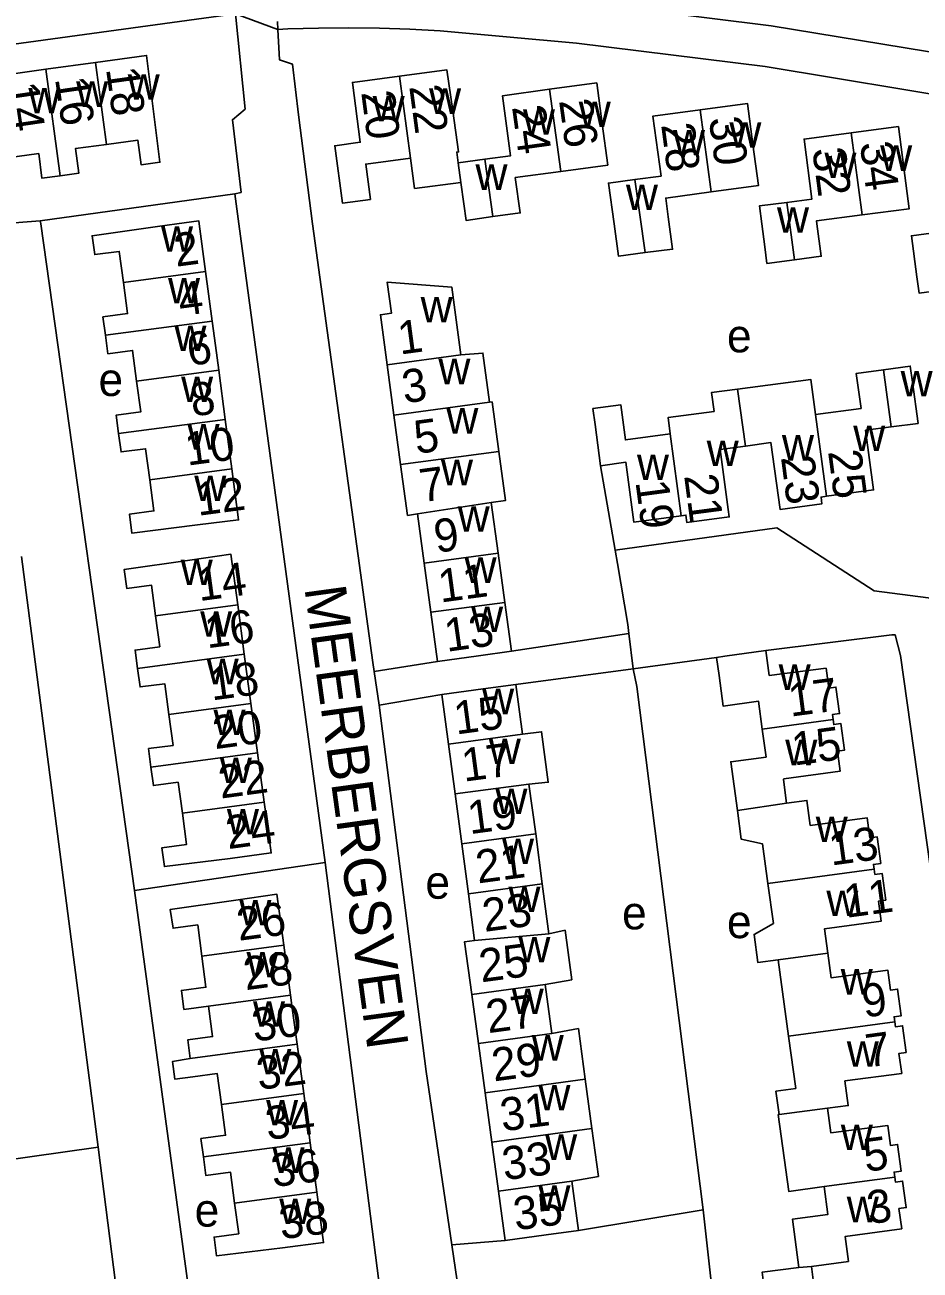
# Model space of a CAD drawing. Extents: x 162667 to 164645, y 379003 to 382150.
# Drawn here: x 163512.2 to 163620.3, y 381373.6 to 381524 of the extents above; entities that cross this region are included whole.
import ezdxf

# ---------------------------------------------------------------- set-up
doc = ezdxf.new("R2010")
doc.units = 0
for name, color, linetype in [('BLT_Basislijn', 7, 'Continuous'), ('BLT_Bebouwing', 7, 'Continuous'), ('BLT_Centroide', 7, 'Continuous'), ('BLT_Huisnummer', 7, 'Continuous'), ('BLT_Huisnummer_ tussenligend', 7, 'Continuous'), ('BLT_Onderverdeling_panden', 7, 'Continuous'), ('BLT_Straatnaam', 7, 'Continuous'), ('BLT_Vlakafsluiter', 7, 'Continuous')]:
    doc.layers.add(name, color=color, linetype=linetype)

msp = doc.modelspace()

# ---------------------------------------------------------------- linework, layer by layer
at = {"layer": 'BLT_Basislijn'}
for p, q in [((163463.77, 381515.19), (163537.61, 381525.38)), ((163542.68, 381524.44), (163542.74, 381523.47)), ((163514.05, 381500.36), (163537.54, 381503.62)), ((163583.46, 381460.55), (163581.71, 381470.77)), ((163511.79, 381459.82), (163521.06, 381388.45)), ((163583.74, 381458.96), (163583.46, 381460.55)), ((163585.13, 381450.52), (163570.94, 381448.36)), ((163585.65, 381446.22), (163585.13, 381450.52)), ((163562.03, 381447.1), (163554.38, 381445.93)), ((163585.65, 381446.22), (163571.47, 381444.36)), ((163595.72, 381447.62), (163585.65, 381446.22)), ((163586.09, 381444.1), (163585.65, 381446.22)), ((163554.38, 381445.93), (163554.96, 381441.86)), ((163586.09, 381444.1), (163594.11, 381380.86)), ((163554.96, 381441.86), (163562.56, 381443.15)), ((163525.43, 381419.47), (163548.47, 381422.85)), ((163521.06, 381388.45), (163494.08, 381384.63)), ((163521.06, 381388.45), (163525.14, 381356.45)), ((163579.05, 381378.38), (163594.11, 381380.86)), ((163570.18, 381377.16), (163563.75, 381376.65))]:
    msp.add_line(p, q, dxfattribs=at)
for points in [[(163695.47, 381503.01), (163691.34, 381504.3), (163687.99, 381503.01), (163646.95, 381515.66), (163645.92, 381517.47), (163633.79, 381520.31), (163631.98, 381519.02), (163602.3, 381523.93), (163579.33, 381526.77), (163559.71, 381528.58), (163557.39, 381530.9), (163548.1, 381530.64)], [(163537.54, 381503.62), (163538.29, 381503.78), (163537.26, 381512.56), (163538.81, 381513.86), (163537.61, 381525.38)], [(163562.36, 381523.31), (163558.68, 381523.51), (163555, 381523.64), (163551.32, 381523.68), (163547.63, 381523.64), (163543.95, 381523.53), (163542.74, 381523.47)], [(163542.74, 381523.47), (163542.94, 381519.8), (163544.49, 381519.28), (163545.22, 381513.14)], [(163626.85, 381514.8), (163601.59, 381518.98), (163578.79, 381521.8), (163562.36, 381523.31)], [(163554.38, 381445.93), (163554.23, 381446.99), (163546.92, 381500), (163545.22, 381513.14)], [(163548.47, 381422.85), (163538.02, 381500), (163537.54, 381503.62)], [(163514.05, 381500.36), (163509.36, 381500), (163506.18, 381499.41), (163469.04, 381494.73)], [(163525.43, 381419.47), (163514.1, 381500), (163514.05, 381500.36)], [(163583.46, 381460.55), (163603.02, 381463.27), (163614.74, 381455.64), (163626.86, 381454.08), (163629.01, 381451.73)], [(163585.13, 381450.52), (163585.01, 381451.58), (163583.74, 381458.96)], [(163601.69, 381448.44), (163616.89, 381450.36), (163617.28, 381450.36), (163617.92, 381447.83)], [(163597.38, 381354.51), (163624.3, 381367.55), (163625.32, 381368.34), (163627.93, 381373.27), (163622.38, 381416.41), (163617.92, 381447.83)], [(163563.75, 381376.65), (163560.66, 381397.6), (163554.96, 381441.86)], [(163558.76, 381347.79), (163555.53, 381367.55), (163548.47, 381422.85)], [(163525.43, 381419.47), (163536.32, 381339.09), (163536.74, 381334.47), (163537.42, 381330.93), (163538.12, 381330.74)], [(163594.11, 381380.86), (163595.35, 381369.64)], [(163563.75, 381376.65), (163566.41, 381358.55), (163567.91, 381350.65), (163567.04, 381348.89), (163567.83, 381346.34)]]:
    msp.add_lwpolyline(points, dxfattribs=at)
at = {"layer": 'BLT_Bebouwing'}
for p, q in [((163514.7, 381518.66), (163508.76, 381517.84)), ((163520.73, 381519.49), (163514.7, 381518.66)), ((163567.75, 381507.79), (163564.51, 381507.35)), ((163534.8, 381488.25), (163534, 381494.22)), ((163536.38, 381476.37), (163535.6, 381482.31)), ((163556.76, 381476.89), (163555.94, 381482.95)), ((163537.18, 381470.38), (163536.38, 381476.37)), ((163557.57, 381470.91), (163556.76, 381476.89)), ((163560.43, 381459.01), (163559.62, 381464.96)), ((163569.35, 381460.21), (163570.15, 381454.26)), ((163561.23, 381453.06), (163560.43, 381459.01)), ((163537.89, 381453.97), (163538.69, 381448.02)), ((163570.15, 381454.26), (163570.94, 381448.36)), ((163562.03, 381447.1), (163561.23, 381453.06)), ((163538.69, 381448.02), (163539.49, 381442.06)), ((163596.02, 381445.41), (163595.72, 381447.62)), ((163572.27, 381438.34), (163571.47, 381444.36)), ((163539.49, 381442.06), (163540.29, 381436.1)), ((163562.56, 381443.15), (163563.36, 381437.15)), ((163540.29, 381436.1), (163541.1, 381430.12)), ((163563.36, 381437.15), (163564.16, 381431.12)), ((163603.85, 381432.95), (163603.79, 381432.86)), ((163573.88, 381426.28), (163573.07, 381432.31)), ((163564.16, 381431.12), (163564.96, 381425.09)), ((163574.68, 381420.25), (163573.88, 381426.28)), ((163564.96, 381425.09), (163565.76, 381419.06)), ((163565.76, 381419.06), (163566.5, 381413.42)), ((163543.45, 381412.85), (163544.27, 381406.8)), ((163575.83, 381402.17), (163575.02, 381408.11)), ((163566.15, 381406.91), (163566.96, 381400.96)), ((163545.07, 381400.89), (163545.86, 381394.93)), ((163566.96, 381400.96), (163567.76, 381395.02)), ((163580.67, 381390.71), (163579.87, 381396.66)), ((163545.86, 381394.93), (163546.65, 381388.98)), ((163567.76, 381395.02), (163568.57, 381389.07)), ((163568.57, 381389.07), (163569.37, 381383.13)), ((163546.65, 381388.98), (163547.44, 381383.02)), ((163569.37, 381383.13), (163570.18, 381377.16)), ((163579.05, 381378.38), (163578.25, 381384.33))]:
    msp.add_line(p, q, dxfattribs=at)
for points in [[(163522.06, 381509.59), (163525.82, 381510.1), (163526.22, 381507.13), (163528.5, 381507.43), (163526.89, 381520.33), (163520.73, 381519.49)], [(163564.51, 381507.35), (163564.34, 381508.66), (163564.56, 381508.68), (163563.86, 381513.64), (163563.16, 381518.59), (163557.45, 381517.83)], [(163557.45, 381517.83), (163551.74, 381517.07), (163552.7, 381509.84), (163549.62, 381509.43), (163550.54, 381502.49), (163553.91, 381502.94), (163553.35, 381507.2), (163558.76, 381507.92)], [(163576.92, 381506.33), (163582.58, 381507.09), (163581.92, 381512.07), (163581.26, 381517.02), (163575.56, 381516.24)], [(163575.56, 381516.24), (163569.86, 381515.45), (163570.85, 381508.22), (163567.75, 381507.79)], [(163595.08, 381503.85), (163600.78, 381504.61), (163600.11, 381509.58), (163599.44, 381514.53), (163593.74, 381513.77)], [(163585.85, 381505.34), (163589.02, 381505.76), (163588.04, 381513), (163593.74, 381513.77)], [(163604.19, 381502.58), (163607.24, 381502.99), (163606.29, 381510.22), (163611.98, 381510.98)], [(163613.29, 381501.06), (163618.99, 381501.82), (163618.34, 381506.77), (163617.68, 381511.73), (163611.98, 381510.98)], [(163516.47, 381505.81), (163518.7, 381506.11), (163518.3, 381509.09), (163522.06, 381509.59)], [(163510.11, 381507.97), (163513.86, 381508.48), (163514.25, 381505.5), (163516.47, 381505.81)], [(163558.76, 381507.92), (163559.25, 381504.27), (163564.84, 381505)], [(163564.84, 381505), (163565.2, 381502.4), (163565.47, 381500.41), (163568.69, 381500.86)], [(163568.69, 381500.86), (163572.01, 381501.31), (163571.42, 381505.58), (163576.92, 381506.33)], [(163587.12, 381496.51), (163583.86, 381496.09), (163583.34, 381500), (163582.67, 381504.91), (163585.85, 381505.34)], [(163595.08, 381503.85), (163589.58, 381503.1), (163589.89, 381500.83), (163590.41, 381496.93), (163587.12, 381496.51)], [(163605.13, 381495.65), (163601.81, 381495.21), (163601.55, 381497.2), (163601.18, 381500), (163600.9, 381502.15), (163604.19, 381502.58)], [(163534, 381494.22), (163533.22, 381500), (163533.18, 381500.36), (163530.54, 381500), (163528.22, 381499.68), (163520.31, 381498.55), (163520.62, 381496.27), (163523.59, 381496.66), (163524.09, 381492.9)], [(163613.29, 381501.06), (163607.79, 381500.34), (163607.83, 381500), (163608.36, 381496.07), (163605.13, 381495.65)], [(163622.54, 381499), (163619.26, 381498.56), (163619.92, 381493.6), (163620.18, 381491.62), (163623.48, 381492.06)], [(163524.09, 381492.9), (163524.6, 381489.14), (163521.62, 381488.75), (163521.92, 381486.53)], [(163555.94, 381482.95), (163555.13, 381489.01), (163556.46, 381489.19), (163555.96, 381492.96), (163563.75, 381492.35), (163564.04, 381490.21), (163564.85, 381484.15)], [(163535.6, 381482.31), (163535.2, 381485.3), (163534.8, 381488.25)], [(163521.92, 381486.53), (163522.22, 381484.3), (163525.19, 381484.7), (163525.68, 381480.98)], [(163564.85, 381484.15), (163567.51, 381484.37), (163568.31, 381478.45)], [(163615.87, 381482.37), (163612.6, 381481.93), (163613.17, 381477.69), (163607.67, 381476.95)], [(163616.8, 381475.46), (163620.05, 381475.89), (163619.38, 381480.85), (163619.12, 381482.8), (163615.87, 381482.37)], [(163525.68, 381480.98), (163526.18, 381477.27), (163523.21, 381476.87), (163523.51, 381474.65)], [(163607.67, 381476.95), (163607.67, 381476.95), (163607.1, 381481.2), (163598.26, 381480.02)], [(163598.26, 381480.02), (163595.11, 381479.6), (163595.42, 381477.33), (163589.87, 381476.59), (163590.13, 381474.61)], [(163568.31, 381478.45), (163568.62, 381478.47), (163569.42, 381472.5)], [(163581.71, 381470.77), (163581.05, 381475.73), (163580.79, 381477.68), (163584.15, 381478.14), (163584.71, 381473.89), (163590.13, 381474.61)], [(163608.98, 381467.08), (163614.69, 381467.84), (163613.72, 381475.05), (163616.8, 381475.46)], [(163523.51, 381474.65), (163523.8, 381472.43), (163526.77, 381472.83), (163527.27, 381469.07)], [(163608.98, 381467.08), (163608.34, 381466.99), (163608.45, 381466.18), (163603.4, 381465.49), (163602.28, 381473.56), (163599.21, 381473.14)], [(163569.42, 381472.5), (163570.22, 381466.56), (163568.52, 381466.34)], [(163599.21, 381473.14), (163596.14, 381472.71), (163597.14, 381465.47), (163597.26, 381464.58), (163592.15, 381463.9), (163592.03, 381464.8), (163591.44, 381464.72)], [(163527.27, 381469.07), (163527.77, 381465.3), (163524.81, 381464.91), (163525.11, 381462.62), (163533.03, 381463.61), (163537.99, 381464.23), (163537.18, 381470.38)], [(163559.62, 381464.96), (163558.4, 381464.77), (163557.57, 381470.91)], [(163591.44, 381464.72), (163585.73, 381463.97), (163584.77, 381471.18), (163581.71, 381470.77)], [(163568.52, 381466.34), (163569.35, 381460.21)], [(163537.89, 381453.97), (163537.07, 381460.08), (163532.12, 381459.37), (163524.18, 381458.22), (163524.49, 381455.94), (163527.47, 381456.34), (163527.97, 381452.62)], [(163527.97, 381452.62), (163528.48, 381448.91), (163525.5, 381448.5), (163525.8, 381446.27)], [(163570.94, 381448.36), (163566.98, 381447.8), (163562.03, 381447.1)], [(163595.72, 381447.62), (163596.74, 381447.76), (163601.69, 381448.44)], [(163601.69, 381448.44), (163602.09, 381445.43), (163608.94, 381446.33)], [(163525.8, 381446.27), (163526.11, 381444.04), (163529.08, 381444.44), (163529.59, 381440.72)], [(163608.94, 381446.33), (163609.27, 381443.91), (163610.14, 381444.03), (163610.58, 381440.82), (163609.71, 381440.7), (163609.79, 381440.1)], [(163601.24, 381438.95), (163600.79, 381442.32), (163596.52, 381441.74), (163596.02, 381445.41)], [(163571.47, 381444.36), (163567.52, 381443.83), (163562.56, 381443.15)], [(163529.59, 381440.72), (163530.09, 381436.99), (163527.12, 381436.59), (163527.42, 381434.36)], [(163597.84, 381432.06), (163597.44, 381435), (163601.7, 381435.58), (163601.24, 381438.95)], [(163609.79, 381440.1), (163609.87, 381439.49), (163610.74, 381439.61), (163611.18, 381436.41), (163610.31, 381436.29), (163610.64, 381433.87), (163603.85, 381432.95)], [(163573.07, 381432.31), (163575.4, 381432.53), (163574.6, 381438.64), (163572.27, 381438.34)], [(163527.42, 381434.36), (163527.72, 381432.12), (163530.7, 381432.53), (163531.21, 381428.78)], [(163603.79, 381432.86), (163604.18, 381430.01)], [(163598.24, 381429.11), (163597.84, 381432.06)], [(163531.21, 381428.78), (163531.71, 381425.02), (163528.74, 381424.62), (163529.05, 381422.34), (163536.98, 381423.3), (163541.94, 381423.99), (163541.32, 381428.49), (163541.1, 381430.12)], [(163604.18, 381430.01), (163606.63, 381430.34), (163607.04, 381427.32), (163613.9, 381428.25), (163614.23, 381425.82), (163615.11, 381425.94), (163615.55, 381422.72), (163614.67, 381422.6), (163614.75, 381422.03)], [(163601.93, 381420.29), (163601.28, 381425.08), (163598.71, 381425.64), (163598.24, 381429.11)], [(163614.75, 381422.03), (163614.84, 381421.39), (163615.71, 381421.51), (163616.15, 381418.3), (163615.28, 381418.18), (163615.61, 381415.75), (163608.77, 381414.83), (163609.16, 381411.89)], [(163575.48, 381414.22), (163574.68, 381420.25)], [(163603.18, 381411.08), (163600.72, 381410.74), (163600.26, 381414.14), (163602.59, 381415.47), (163601.93, 381420.29)], [(163543.45, 381412.85), (163542.62, 381419), (163537.67, 381418.29), (163529.75, 381417.16), (163530.09, 381414.9), (163533.06, 381415.29), (163533.56, 381411.53)], [(163575.02, 381408.11), (163578.24, 381408.68), (163577.43, 381414.65), (163575.48, 381414.22)], [(163566.5, 381413.42), (163565.29, 381413.27), (163566.15, 381406.91)], [(163609.16, 381411.89), (163609.56, 381408.91), (163616.4, 381409.83), (163616.72, 381407.42), (163617.59, 381407.54), (163618.03, 381404.32), (163617.16, 381404.21), (163617.24, 381403.6)], [(163533.56, 381411.53), (163534.06, 381407.77), (163531.09, 381407.38), (163531.39, 381405.08), (163534.37, 381405.48)], [(163604.43, 381401.87), (163603.18, 381411.08)], [(163544.27, 381406.8), (163544.48, 381405.25), (163545.07, 381400.89)], [(163534.37, 381405.48), (163534.86, 381401.81), (163531.86, 381401.41), (163532.16, 381399.17)], [(163579.87, 381396.66), (163579.04, 381402.78), (163575.83, 381402.17)], [(163617.24, 381403.6), (163617.32, 381403), (163618.19, 381403.12), (163618.62, 381399.9), (163617.75, 381399.78), (163618.08, 381397.36), (163611.23, 381396.45), (163611.62, 381393.48), (163609.14, 381393.16)], [(163603.28, 381392.39), (163602.9, 381395.21), (163605.28, 381395.54), (163604.43, 381401.87)], [(163532.16, 381399.17), (163530.02, 381398.8), (163530.31, 381396.65), (163532.46, 381396.93), (163535.43, 381397.33), (163535.93, 381393.61)], [(163535.93, 381393.61), (163536.43, 381389.89), (163533.45, 381389.49), (163533.75, 381387.26)], [(163608.7, 381383.68), (163604.44, 381383.1), (163603.18, 381392.38), (163603.28, 381392.39)], [(163609.14, 381393.16), (163609.54, 381390.17), (163616.39, 381391.08), (163616.72, 381388.65), (163617.59, 381388.77), (163618.03, 381385.56), (163617.16, 381385.44), (163617.24, 381384.83)], [(163578.25, 381384.33), (163581.46, 381384.92), (163580.67, 381390.71)], [(163533.75, 381387.26), (163534.04, 381385.03), (163537.02, 381385.43), (163537.52, 381381.7)], [(163617.24, 381384.83), (163617.32, 381384.23), (163618.19, 381384.35), (163618.63, 381381.14), (163617.75, 381381.02), (163618.08, 381378.59), (163611.26, 381377.66), (163611.64, 381374.65), (163607.17, 381374.05)], [(163537.52, 381381.7), (163538.01, 381377.98), (163535.04, 381377.59), (163535.34, 381375.3), (163543.3, 381376.29), (163548.26, 381376.91), (163547.44, 381383.02)], [(163605.67, 381373.93), (163604.88, 381379.73), (163609.15, 381380.31), (163608.7, 381383.68)], [(163570.18, 381377.16), (163575.13, 381377.84), (163579.05, 381378.38)], [(163607.17, 381374.05), (163607.56, 381371.12), (163614.42, 381372.04), (163614.74, 381369.62), (163615.6, 381369.74), (163616.03, 381366.53), (163615.17, 381366.41), (163615.28, 381365.62), (163606.74, 381364.44), (163606.27, 381367.99), (163602.02, 381367.42), (163601.35, 381372.38), (163601.22, 381373.33), (163605.67, 381373.93)]]:
    msp.add_lwpolyline(points, dxfattribs=at)
at = {"layer": 'BLT_Onderverdeling_panden'}
for p, q in [((163516.47, 381505.81), (163514.7, 381518.66)), ((163522.06, 381509.59), (163520.73, 381519.49)), ((163557.45, 381517.83), (163558.76, 381507.92)), ((163575.56, 381516.24), (163576.92, 381506.33)), ((163593.74, 381513.77), (163595.08, 381503.85)), ((163611.98, 381510.98), (163613.29, 381501.06)), ((163564.51, 381507.35), (163564.84, 381505)), ((163568.69, 381500.86), (163567.75, 381507.79)), ((163587.12, 381496.51), (163585.85, 381505.34)), ((163605.13, 381495.65), (163604.19, 381502.58)), ((163524.09, 381492.9), (163534, 381494.22)), ((163521.92, 381486.53), (163534.8, 381488.25)), ((163564.85, 381484.15), (163555.94, 381482.95)), ((163525.68, 381480.98), (163535.6, 381482.31)), ((163616.8, 381475.46), (163615.87, 381482.37)), ((163599.21, 381473.14), (163598.26, 381480.02)), ((163568.31, 381478.45), (163556.76, 381476.89)), ((163523.51, 381474.65), (163536.38, 381476.37)), ((163608.98, 381467.08), (163607.67, 381476.95)), ((163591.44, 381464.72), (163590.13, 381474.61)), ((163569.42, 381472.5), (163557.57, 381470.91)), ((163527.27, 381469.07), (163537.18, 381470.38)), ((163559.62, 381464.96), (163568.52, 381466.34)), ((163569.35, 381460.21), (163560.43, 381459.01)), ((163527.97, 381452.62), (163537.89, 381453.97)), ((163570.15, 381454.26), (163561.23, 381453.06)), ((163525.8, 381446.27), (163538.69, 381448.02)), ((163529.59, 381440.72), (163539.49, 381442.06)), ((163601.24, 381438.95), (163609.79, 381440.1)), ((163572.27, 381438.34), (163563.36, 381437.15)), ((163527.42, 381434.36), (163540.29, 381436.1)), ((163573.07, 381432.31), (163564.16, 381431.12)), ((163531.21, 381428.78), (163541.1, 381430.12)), ((163598.24, 381429.11), (163604.18, 381430.01)), ((163573.88, 381426.28), (163564.96, 381425.09)), ((163601.93, 381420.29), (163614.75, 381422.03)), ((163574.68, 381420.25), (163565.76, 381419.06)), ((163566.5, 381413.42), (163575.48, 381414.22)), ((163533.56, 381411.53), (163543.45, 381412.85)), ((163603.18, 381411.08), (163609.16, 381411.89)), ((163575.02, 381408.11), (163566.15, 381406.91)), ((163534.37, 381405.48), (163544.27, 381406.8)), ((163604.43, 381401.87), (163617.24, 381403.6)), ((163575.83, 381402.17), (163566.96, 381400.96)), ((163532.16, 381399.17), (163545.07, 381400.89)), ((163579.87, 381396.66), (163567.76, 381395.02)), ((163535.93, 381393.61), (163545.86, 381394.93)), ((163603.28, 381392.39), (163609.14, 381393.16)), ((163580.67, 381390.71), (163568.57, 381389.07)), ((163533.75, 381387.26), (163546.65, 381388.98)), ((163608.7, 381383.68), (163617.24, 381384.83)), ((163537.52, 381381.7), (163547.44, 381383.02)), ((163578.25, 381384.33), (163569.37, 381383.13)), ((163605.67, 381373.93), (163607.17, 381374.05))]:
    msp.add_line(p, q, dxfattribs=at)
at = {"layer": 'BLT_Vlakafsluiter'}
msp.add_line((163537.61, 381525.38), (163542.74, 381523.47), dxfattribs=at)

# ---------------------------------------------------------------- texts
at = {"layer": 'BLT_Centroide'}
for s, p in [('w', (163518.38, 381514.12)), ('w', (163524.61, 381514.98)), ('w', (163512.61, 381513.34)), ('w', (163554.19, 381512.36)), ('w', (163561, 381513.27)), ('w', (163579.08, 381511.67)), ('w', (163572.34, 381510.75)), ('w', (163590.47, 381508.27)), ('w', (163597.27, 381509.19)), ('w', (163615.48, 381506.39)), ('w', (163608.75, 381505.52)), ('w', (163566.61, 381504.09)), ('w', (163584.78, 381501.66)), ('w', (163603.02, 381498.91)), ('w', (163528.63, 381496.62)), ('w', (163529.48, 381490.38)), ('w', (163559.98, 381488.08)), ('w', (163530.25, 381484.62)), ('e', (163596.98, 381484.47)), ('e', (163521.08, 381479.19)), ('w', (163562.13, 381480.62)), ('w', (163531.06, 381478.47)), ('w', (163617.95, 381479.14)), ('w', (163563.09, 381474.66)), ('w', (163531.83, 381472.72)), ('w', (163612.23, 381472.53)), ('w', (163594.53, 381470.72)), ('w', (163603.62, 381471.39)), ('w', (163586.11, 381469.05)), ('w', (163562.44, 381468.41)), ('w', (163532.65, 381466.5)), ('w', (163564.46, 381462.81)), ('w', (163531.01, 381456.34)), ('w', (163565.29, 381456.62)), ('w', (163566.09, 381450.69)), ('w', (163533.36, 381450.12)), ('w', (163534.14, 381444.38)), ('w', (163603.22, 381443.69)), ('w', (163567.41, 381440.75)), ('w', (163534.97, 381438.22)), ('w', (163568.22, 381434.72)), ('w', (163604.02, 381434.59)), ('w', (163535.74, 381432.44)), ('w', (163569.02, 381428.69)), ('w', (163536.59, 381426.22)), ('w', (163607.7, 381425.31)), ('w', (163569.82, 381422.66)), ('e', (163560.56, 381418.46)), ('w', (163570.59, 381416.84)), ('w', (163608.98, 381416.38)), ('w', (163538.09, 381415.25)), ('e', (163584.31, 381414.76)), ('e', (163596.98, 381413.7)), ('w', (163571.79, 381410.78)), ('w', (163538.95, 381408.97)), ('w', (163610.72, 381406.88)), ('w', (163570.99, 381404.53)), ('w', (163539.74, 381403)), ('w', (163573.4, 381398.91)), ('w', (163611.45, 381398.16)), ('w', (163540.5, 381397.25)), ('w', (163574.21, 381392.88)), ('w', (163541.32, 381391.09)), ('w', (163610.73, 381388.09)), ('w', (163575.02, 381386.91)), ('w', (163542.09, 381385.34)), ('w', (163574.21, 381380.75)), ('e', (163532.69, 381378.85)), ('w', (163542.91, 381379.16)), ('w', (163611.45, 381379.38))]:
    msp.add_text(s, height=4, dxfattribs=at).set_placement(p)
at = {"layer": 'BLT_Huisnummer'}
for s, rotation, p in [('18', 277.844, (163521.98, 381518.72)), ('20', 277.5495, (163552.8, 381515.88)), ('22', 277.5507, (163558.6, 381516.59)), ('24', 277.8493, (163571.01, 381514.12)), ('26', 277.8467, (163576.69, 381514.88)), ('30', 277.6752, (163594.78, 381512.72)), ('28', 277.675, (163589.02, 381511.96)), ('34', 277.5329, (163613.02, 381509.73)), ('32', 277.5251, (163607.27, 381509)), ('2', 7.5943, (163530.45, 381494.8)), ('1', 7.6831, (163557.49, 381484.19)), ('6', 7.5943, (163532.02, 381482.82)), ('5', 7.6856, (163559.46, 381472.19)), ('23', 277.5104, (163603.49, 381471.8)), ('25', 277.5104, (163609.18, 381472.49)), ('12', 7.5943, (163533.1, 381464.71)), ('21', 277.5104, (163591.8, 381469.56)), ('19', 277.5967, (163585.92, 381468.82)), ('9', 7.68, (163561.87, 381460.24)), ('14', 7.7327, (163533.25, 381454.4)), ('13', 8.0361, (163563.14, 381448.28)), ('18', 7.7264, (163534.76, 381442.4)), ('17', 7.485, (163604.65, 381440.45)), ('15', 7.5715, (163564.27, 381438.29)), ('19', 7.5715, (163565.92, 381426.25)), ('24', 7.8611, (163536.73, 381424.44)), ('13', 7.7021, (163609.56, 381422.46)), ('23', 7.5715, (163567.7, 381414.45)), ('26', 7.5745, (163538.02, 381413.37)), ('9', 7.6742, (163613.55, 381404.09)), ('30', 7.5745, (163539.88, 381401.18)), ('27', 7.5715, (163568.14, 381402.21)), ('34', 7.5745, (163541.51, 381389.3)), ('31', 7.5715, (163569.86, 381390.34)), ('5', 7.7652, (163613.73, 381385.45)), ('35', 7.5715, (163571.45, 381378.39)), ('38', 7.5745, (163543.16, 381377.3))]:
    msp.add_text(s, height=4, rotation=rotation, dxfattribs=at).set_placement(p)
at = {"layer": 'BLT_Huisnummer_ tussenligend'}
for s, rotation, p in [('16', 278.3197, (163515.82, 381517.52)), ('14', 278.3197, (163509.85, 381516.84)), ('4', 7.5943, (163530.97, 381488.83)), ('3', 7.6831, (163558, 381478.3)), ('8', 7.5943, (163532.43, 381476.71)), ('10', 7.5943, (163531.81, 381470.77)), ('7', 7.6856, (163560.12, 381466.35)), ('11', 7.68, (163562.38, 381454.23)), ('16', 7.7327, (163534.2, 381448.7)), ('20', 7.7264, (163535.15, 381436.52)), ('15', 7.7021, (163605.08, 381434.54)), ('17', 7.5715, (163565.21, 381432.59)), ('22', 7.7264, (163535.84, 381430.55)), ('21', 7.5715, (163566.9, 381420.3)), ('11', 7.6742, (163611.35, 381416.14)), ('28', 7.5745, (163538.85, 381407.4)), ('25', 7.5715, (163567.3, 381408.35)), ('29', 7.5715, (163568.83, 381396.38)), ('7', 7.7652, (163613.99, 381398.07)), ('32', 7.5745, (163540.43, 381395.35)), ('33', 7.5715, (163570.09, 381384.44)), ('36', 7.5745, (163542.19, 381383.6)), ('3', 7.8669, (163614.15, 381379.13))]:
    msp.add_text(s, height=4, rotation=rotation, dxfattribs=at).set_placement(p)
at = {"layer": 'BLT_Straatnaam'}
msp.add_text('MEERBERGSVEN', height=5, rotation=277.7976, dxfattribs=at).set_placement((163545.94, 381456.01))

doc.saveas('drawing.dxf')
